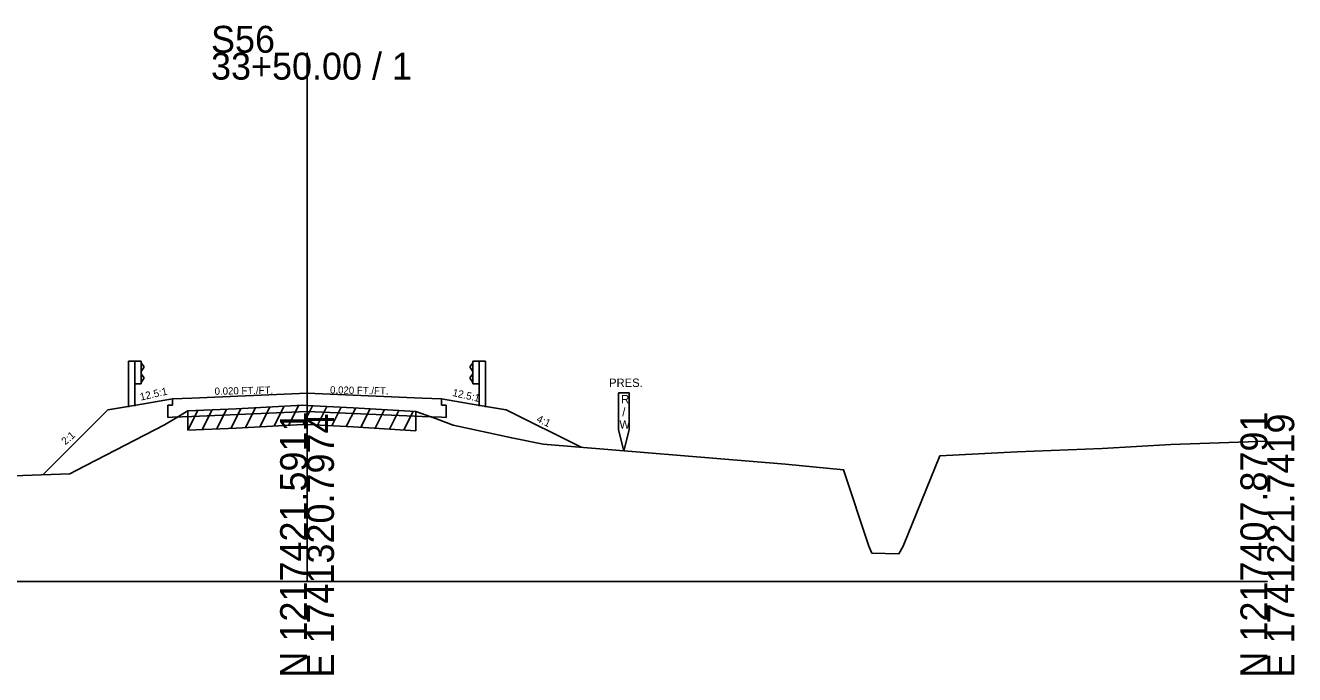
# Model space of a CAD drawing. Extents: x -26 to 1203, y -10 to 19541.
# Drawn here: x 70.7 to 202.8, y 8490.3 to 8557.9 of the extents above; entities that cross this region are included whole.
import ezdxf

# ---------------------------------------------------------------- set-up
doc = ezdxf.new("R2010")
doc.units = 0
for name, color, linetype in [('RD_GPK_XS_Cell', 7, 'Continuous'), ('RD_XS_Base', 7, 'Continuous'), ('RD_XS_EarthShd', 7, 'Continuous'), ('RD_XS_ExGround', 7, 'Continuous'), ('RD_XS_ExPaveRet', 7, 'Continuous'), ('RD_XS_ExRW', 7, 'Continuous'), ('RD_XS_GR', 7, 'Continuous'), ('RD_XS_Pave', 7, 'Continuous'), ('RD_XS_TX_Elev_EX', 7, 'Continuous'), ('RD_XS_TX_Slope', 7, 'Continuous')]:
    doc.layers.add(name, color=color, linetype=linetype)

msp = doc.modelspace()

# ---------------------------------------------------------------- linework, layer by layer
at = {"layer": 'RD_GPK_XS_Cell'}
for p, q in [((100, 8500), (100, 8555.04)), ((0, 8500), (100, 8500)), ((100, 8500), (200, 8500))]:
    msp.add_line(p, q, dxfattribs=at)
at = {"layer": 'RD_XS_Base'}
for p, q in [((86, 8518.37), (86, 8519)), ((114, 8518.37), (114, 8519)), ((86, 8518.37), (85.5, 8518.35)), ((85.5, 8517.08), (85.5, 8518.35)), ((86, 8517.1), (85.5, 8517.08)), ((86, 8517.1), (88, 8517.18)), ((88, 8517.18), (100, 8517.68)), ((112, 8517.18), (100, 8517.68)), ((114, 8517.1), (112, 8517.18)), ((114, 8518.37), (114.5, 8518.35)), ((114, 8517.1), (114.5, 8517.08)), ((114.5, 8517.08), (114.5, 8518.35))]:
    msp.add_line(p, q, dxfattribs=at)
at = {"layer": 'RD_XS_EarthShd'}
for p, q in [((83, 8518.5), (79.25, 8517.88)), ((83, 8518.5), (79.5, 8517.92)), ((86, 8519), (83, 8518.5)), ((114, 8519), (117, 8518.5)), ((117, 8518.5), (120.5, 8517.92)), ((117, 8518.5), (120.75, 8517.88)), ((72.48, 8511.11), (79.25, 8517.88)), ((120.75, 8517.88), (128.54, 8513.98))]:
    msp.add_line(p, q, dxfattribs=at)
at = {"layer": 'RD_XS_ExGround'}
msp.add_lwpolyline([(64.51, 8510.82), (75.3, 8511.21), (75.96, 8511.56), (85.14, 8516.3), (86.09, 8516.86), (87.59, 8517.76), (92.61, 8517.97), (99.55, 8518.35), (100, 8518.33), (104.79, 8518.09), (111.34, 8517.69), (113.47, 8516.93), (115.22, 8516.27), (121.32, 8514.95), (124.58, 8514.31), (149.81, 8512.22), (155.87, 8511.64), (158.51, 8503.66), (158.83, 8502.96), (161.64, 8502.89), (162.09, 8503.69), (165.88, 8513.07), (173.95, 8513.48), (182.79, 8513.84), (189.95, 8514.25), (200, 8514.62)], dxfattribs=at)
at = {"layer": 'RD_XS_ExPaveRet'}
for p, q in [((87.59, 8515.76), (88.61, 8517.8)), ((87.59, 8515.76), (87.59, 8517.76)), ((89.09, 8515.82), (90.11, 8517.87)), ((90.59, 8515.89), (91.61, 8517.93)), ((92.09, 8515.95), (93.12, 8518)), ((93.59, 8516.02), (94.62, 8518.08)), ((95.09, 8516.1), (96.12, 8518.16)), ((96.59, 8516.19), (97.62, 8518.24)), ((98.09, 8516.27), (99.12, 8518.32)), ((99.59, 8516.35), (100.57, 8518.3)), ((101.09, 8516.27), (102.07, 8518.23)), ((102.59, 8516.2), (103.57, 8518.15)), ((104.09, 8516.13), (105.07, 8518.08)), ((105.59, 8516.04), (106.56, 8517.99)), ((107.09, 8515.95), (108.06, 8517.89)), ((108.59, 8515.86), (109.56, 8517.8)), ((110.09, 8515.77), (111.06, 8517.71)), ((111.34, 8517.69), (111.34, 8515.69)), ((87.59, 8515.76), (92.61, 8515.97)), ((92.61, 8515.97), (99.55, 8516.35)), ((99.55, 8516.35), (100, 8516.33)), ((100, 8516.33), (104.79, 8516.09)), ((104.79, 8516.09), (111.34, 8515.69))]:
    msp.add_line(p, q, dxfattribs=at)
at = {"layer": 'RD_XS_ExRW'}
msp.add_lwpolyline([(132.45, 8519.63), (133.55, 8519.63), (133.55, 8515.8), (133, 8513.61), (132.45, 8515.8)], close=True, dxfattribs=at)
at = {"layer": 'RD_XS_GR'}
for p, q in [((81.4, 8522.92), (81.4, 8518.15)), ((82.06, 8522.92), (81.4, 8522.92)), ((82.06, 8522.92), (82.06, 8518.26)), ((82.73, 8522.92), (82.06, 8522.92)), ((82.73, 8520.59), (82.73, 8522.92)), ((82.73, 8522.77), (83, 8522.37)), ((83, 8522.37), (83, 8522.27)), ((117.27, 8522.77), (117, 8522.37)), ((117, 8522.37), (117, 8522.27)), ((117.27, 8520.59), (117.27, 8522.92)), ((117.27, 8522.92), (117.94, 8522.92)), ((117.94, 8522.92), (117.94, 8518.26)), ((117.94, 8522.92), (118.6, 8522.92)), ((118.6, 8522.92), (118.6, 8518.15)), ((83, 8522.27), (82.73, 8521.87)), ((83, 8521.23), (82.73, 8521.63)), ((82.73, 8520.73), (83, 8521.13)), ((83, 8521.13), (83, 8521.23)), ((117, 8522.27), (117.27, 8521.87)), ((117, 8521.23), (117.27, 8521.63)), ((117, 8521.13), (117, 8521.23)), ((117.27, 8520.73), (117, 8521.13)), ((82.73, 8520.59), (82.06, 8520.59)), ((117.27, 8520.59), (117.94, 8520.59))]:
    msp.add_line(p, q, dxfattribs=at)
at = {"layer": 'RD_XS_Pave'}
for p, q in [((86, 8519), (88, 8519.09)), ((88, 8519.09), (100, 8519.59)), ((112, 8519.09), (100, 8519.59)), ((114, 8519), (112, 8519.09))]:
    msp.add_line(p, q, dxfattribs=at)

# ---------------------------------------------------------------- texts
at = {"layer": 'RD_GPK_XS_Cell'}
for s, p in [('S56', (90, 8555.04)), ('33+50.00 / 1', (90, 8552.24))]:
    msp.add_text(s, height=2.8, dxfattribs=at).set_placement(p)
for s, p in [('N 1217421.5911', (100, 8490)), ('E 1741320.7974', (102.8, 8490)), ('N 1217407.8791', (200, 8490)), ('E 1741221.7419', (202.8, 8490))]:
    msp.add_text(s, height=2.8, rotation=90, dxfattribs=at).set_placement(p)
at = {"layer": 'RD_XS_ExRW'}
for s, p in [('PRES.', (131.45, 8520.25)), ('R', (132.71, 8518.54)), ('/', (132.83, 8517.22)), ('W', (132.53, 8515.91))]:
    msp.add_text(s, height=0.875, dxfattribs=at).set_placement(p)
at = {"layer": 'RD_XS_TX_Elev_EX'}
msp.add_text('845.16', height=0.1, rotation=90, dxfattribs=at).set_placement((100.1, 8518.33))
at = {"layer": 'RD_XS_TX_Slope'}
for s, height, rotation, p in [('12.5:1', 0.778, 12.7511, (82.69, 8518.82)), ('0.020 FT./FT.', 0.7518, 1.1916, (90.38, 8519.43)), ('0.020 FT./FT.', 0.7518, 358.8084, (102.39, 8519.58)), ('12.5:1', 0.778, 347.2489, (115.09, 8519.32)), ('4:1', 0.778, 335.081, (123.83, 8516.66)), ('2:1', 0.778, 40.6589, (74.83, 8514.17))]:
    msp.add_text(s, height=height, rotation=rotation, dxfattribs=at).set_placement(p)

doc.saveas('drawing.dxf')
